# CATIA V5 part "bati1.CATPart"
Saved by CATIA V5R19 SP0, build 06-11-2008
Part number: bati
Publications: "D-vis/goupille1"
Bounding box of the stored display mesh (mm): x -124.81 to 14.958, y -77.935 to 32.116, z 0 to 5
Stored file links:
  C:\Documents and Settings\alenoir\Bureau\mécanisme\bati1.CATPart
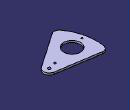
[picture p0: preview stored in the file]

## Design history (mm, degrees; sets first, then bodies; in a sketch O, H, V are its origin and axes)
Parameters
  `D-vis/goupille1` = 20 mm
  LENGTH = 0 mm
Body1 (main body)
  Sketch1 on xy-plane, origin (0, 0, 0), H (0.2216, -0.9751, 0), V (0.9751, 0.2216, 0)
    line L1 (-13.9342, 5.5533) -> (-55.2099, -98.0146)
    line L2 (13.9342, 5.5533) -> (55.2099, -98.0146)
    construction line L3 (0, -344.6302) -> (0, 309.6302)
    point P1 (0, -344.6302)
    point P3 (16.1474, 0)
    point P4 (0, 200)
    circle A1 centre (0, 0) radius 4
    arc A2 centre (0, 0) radius 125 from (-47.8354, -115.4849) to (47.8354, -115.4849) ccw
    arc A3 centre (0, 0) radius 15 from (13.9342, 5.5533) to (-13.9342, 5.5533) ccw
    point P5 (0, 0)
    arc A4 centre (42.6692, -103.0126) radius 13.5 from (47.8354, -115.4849) to (55.2099, -98.0146) ccw
    arc A5 centre (-42.6692, -103.0126) radius 13.5 from (-47.8354, -115.4849) to (-55.2099, -98.0146) cw
    circle A6 centre (0, -115) radius 2.5
    point P14 (0, -115)
    circle A7 centre (0, -20) radius 2.5
    point P15 (0, -20)
    point P16 (0, -17.5)
    circle A8 centre (0, -80) radius 22.3607
    point P17 (0, -80)
    construction line L4 (0, 0) -> (-42.6692, -103.0126)
    construction line L5 (0, 0) -> (42.6692, -103.0126)
    radius A1 = 4
    radius A2 = 125
    radius A5 = 13.5
    radius A6 = 2.5
    radius A7 = 2.5
    distance O P15 = 20 {= `D-vis/goupille1`}
    distance O P14 = 115
    radius A8 = 22.3607
    distance P17 O = 80
    radius A3 = 15
    angle L4 L5 = 45
    angle L3 L5 = 22.5
    radius A4 = 13.5
    coincidence: P1 V, P3 L2, P3 H, P14 L3, P15 L3, A7 P16, P5 O, P17 L3
    vertical: L3 V
    tangency: A3 L1, A3 L2, A4 L2, A4 A2, A5 A2, A5 L1
    midpoint: P16 L3
    fix: L3
  Pad1: profile Sketch1, direction (0, 0, 1), length 5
